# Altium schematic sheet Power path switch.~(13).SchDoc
size A3; SheetNumber: 6; SheetTotal: 7
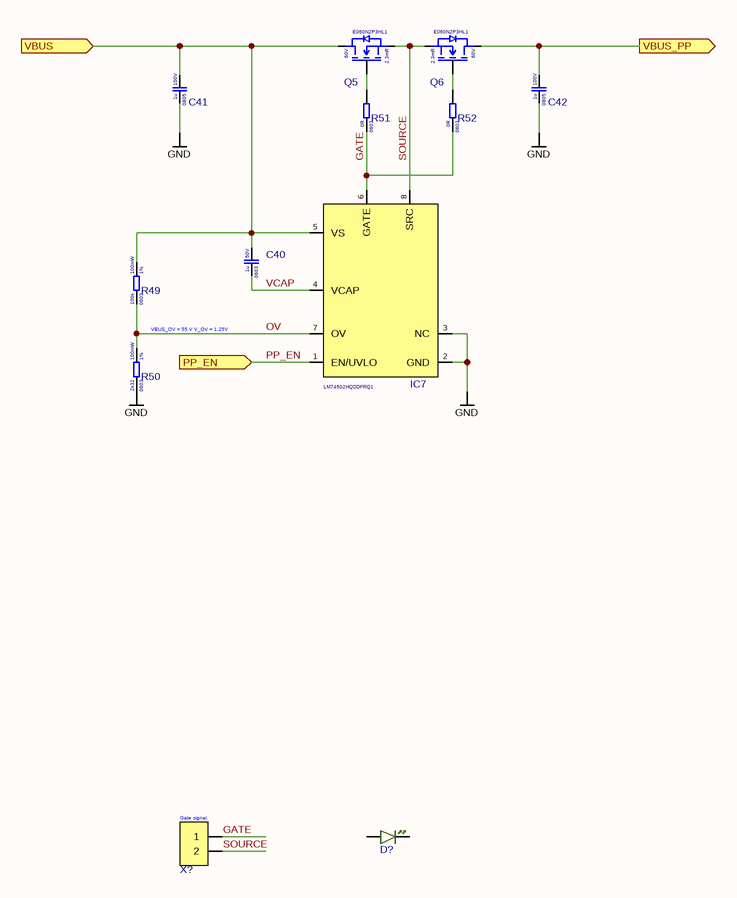
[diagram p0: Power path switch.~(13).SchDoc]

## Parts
C40  Voltage Rating: 50V  Case Code (Imperial): 0603  Capacitance: 1u  [CAP 0603]  (hidden comment: CL10A105KB8NNNC)
C41  Voltage Rating: 100V  Case Code (Imperial): 0805  Capacitance: 1u  [Cap_0805]  (hidden comment: CC0805KKX7R0BB105)
C42  Voltage Rating: 100V  Case Code (Imperial): 0805  Capacitance: 1u  [Cap_0805]  (hidden comment: CC0805KKX7R0BB105)
D?  PSC-1608U52GC-G4  [DIODE_0603]  (value not drawn)
IC7  LM74502HQDDFRQ1  [SOT-23-8]
Q5  Rds: 2.3mR  Voltage: 60V  [DFN-8 (5x6)]  (hidden comment: E060N2P3HL1)
Q6  Rds: 2.3mR  Voltage: 60V  [DFN-8 (5x6)]  (hidden comment: E060N2P3HL1)
R49  Resistance Tolerance: 1%  Resistance: 100k  Power Rating: 100mW  Case Code (Imperial): 0603  [RES_0603]  (hidden comment: 0603WAF1003T5E)
R50  Resistance Tolerance: 1%  Resistance: 2k32  Power Rating: 100mW  Case Code (Imperial): 0603  [RES_0603]  (hidden comment: FRC0603F2321TS)
R51  Resistance: 0R  Case Code (Imperial): 0603  [RES_0603]  (hidden comment: 0603WAF0000T5E)
R52  Resistance: 0R  Case Code (Imperial): 0603  [RES_0603]  (hidden comment: 0603WAF0000T5E)
X?  ZX-PZ1.27-1-2PZZ  [Pin header 1x2 1.27mmP THT Vertical]  (value not drawn)

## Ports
PP_EN (in, see Arhitecture[4A], USB PD[6A]), VBUS (in, see Arhitecture[3A], USB protection[3B]), VBUS_PP (out, see Arhitecture[4A])

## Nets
GND: C41.1 C42.1 IC7.2(GND) IC7.3(NC) R50.1
GATE: IC7.6(GATE) R51.1 R52.1 X?.1
OV: IC7.7(OV) R49.1 R50.2
PP_EN: IC7.1(EN/UVLO) ; port PP_EN
SOURCE: IC7.8(SRC) Q5.S Q6.S X?.2
VBUS: C40.2 C41.2 IC7.5(VS) Q5.D R49.2 ; port VBUS
VBUS_PP: C42.2 Q6.D ; port VBUS_PP
VCAP: C40.1 IC7.4(VCAP)
NetQ5_G: Q5.G R51.2
NetQ6_G: Q6.G R52.2

Not connected (* = marked no-connect by the designer): D? A K

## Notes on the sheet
- VBUS_OV = 55 V V_OV = 1.25V
- (near X?) Gate signal.

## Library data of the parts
C40 = CL10A105KB8NNNC: Cap 1uF 50V 0603 X5R; Manufacturer: Samsung
C41 C42 = CC0805KKX7R0BB105: Cap 1uF 100V 0805 X7R; Manufacturer: Yageo
D? = PSC-1608U52GC-G4: LED Green 0603 20mA; Manufacturer: HONGLITRONIC
IC7 = LM74502HQDDFRQ1: High-side switch controller IC 3.2~65V Reverse polarity protection; Manufacturer: Texas Instruments
Q5 Q6 = E060N2P3HL1: Nmos 60V 180A 2.3mR PDFN5x6-8; Manufacturer: Existar
R49 = 0603WAF1003T5E: Res 100k 0603 1% 100mW 75V; Manufacturer: Uni-Royal
R50 = FRC0603F2321TS: Res 2k32 0603 1% 100mW 75V; Manufacturer: Uni-Royal
R51 R52 = 0603WAF0000T5E: Res 0R 0603 1% 100mW 75V; Manufacturer: UNI-ROYAL
X? = ZX-PZ1.27-1-2PZZ: Pin header 1x2 1.27mmP THT Vertical; Manufacturer: Megastar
